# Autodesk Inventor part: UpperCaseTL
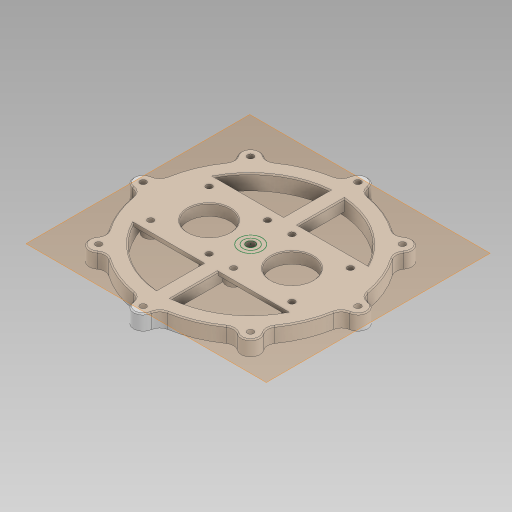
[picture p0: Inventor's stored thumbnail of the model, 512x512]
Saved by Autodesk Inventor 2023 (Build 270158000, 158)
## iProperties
Created: 2024-05
Part Number: UpperCaseTL
Material: 一般
Document SubType Name: Modeling
Designer: kumagai
Density: 1 g/cm^3
Appearance: 既定
Author: kumagai
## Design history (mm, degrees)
derived "UpperCase.ipt"
  sketch "スケッチ5"
    geometry: C1 r 4 at (54, 0) reference; C2 r 6 at (54, 0) reference; C3 r 2.25 at (54, 0) reference; 1 further point
  node "MotorFace"
sketch "スケッチ2"
  geometry: L1 (-86.8, -57)-(86.8, -57) reference; L2 (-40.927, -36)-(40.927, -36); L3 (-40.927, -78)-(40.927, -78); L4 (-4, -38.378)-(-4, -11.174) reference; L5 (4, -38.378)-(4, -11.174) reference; L6 (-4, -102.826)-(-4, -75.622) reference; L7 (4, -102.826)-(4, -75.622) reference; 6 further points
  constraints: 4 end point, 2 horizontal, 6 other
  dimensions: "d1" = 42 distance between parallel lines of L3 L2
extrude "押し出し1" cut sketch "スケッチ2" extent not by distance; stored distance "d2" = 0; taper "d3" = 0 deg
chamfer "面取り1" distance "d4" = 0.6; stored, may be unused: second distance "d5" = 2, angle "d6" = 45 deg
feature "ソリッド1::UpperCase.ipt" dims "d0" = 10
tag "TaggingFeature1"
node "ソリッド1"
